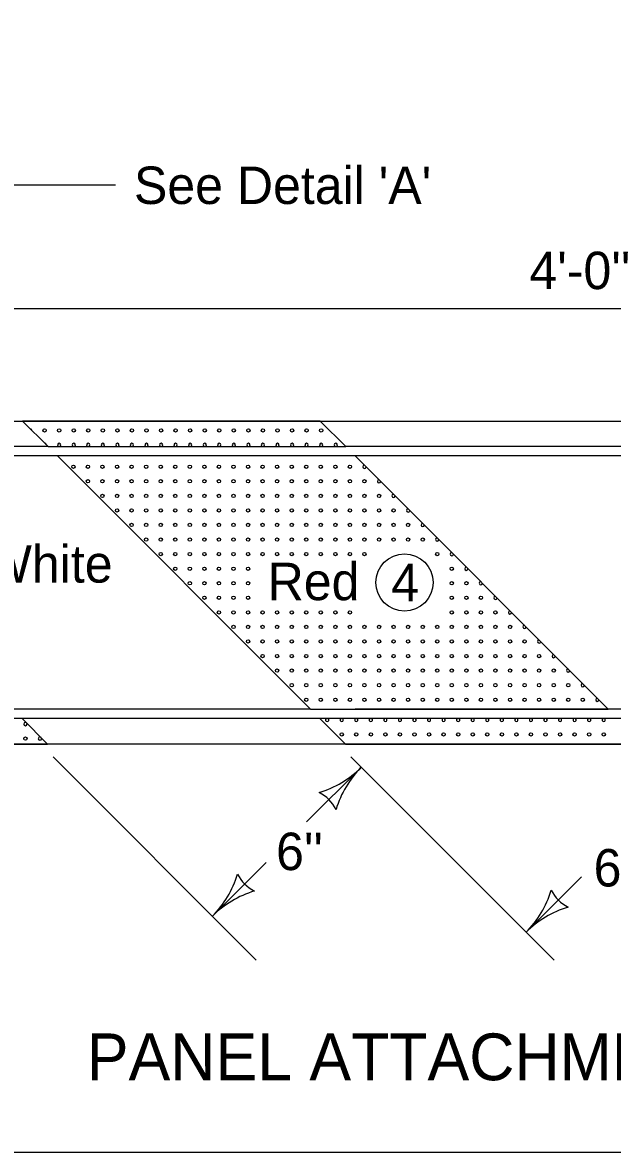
# Model space of a CAD drawing. Extents: x 228 to 3572, y -1307 to 1277.
# Drawn here: x 1955.3 to 2207.4, y -1020 to -537.2 of the extents above; entities that cross this region are included whole.
import ezdxf

# ---------------------------------------------------------------- set-up
doc = ezdxf.new("R2010")
doc.units = 0
for name, color, linetype in [('dsnStdBorder', 7, 'Continuous'), ('dsnStdDimension', 7, 'Continuous'), ('Level 2', 7, 'Continuous'), ('Level 3', 7, 'Continuous')]:
    doc.layers.add(name, color=color, linetype=linetype)

msp = doc.modelspace()

# ---------------------------------------------------------------- linework, layer by layer
at = {"layer": 'dsnStdBorder'}
msp.add_lwpolyline([(332.48, 990.01), (3467.48, 990.01), (3467.48, -1019.99), (332.48, -1019.99)], close=True, dxfattribs=at)
at = {"layer": 'dsnStdDimension'}
for p, q in [((1949.92, -606.46), (1995.05, -606.46)), ((2559.99, -659.46), (1827.99, -659.46)), ((2055.2, -937.89), (1968.29, -850.98)), ((2182.48, -937.89), (2095.57, -850.98)), ((2076.7, -878.78), (2100.05, -855.43)), ((2036.41, -919.06), (2059.41, -896.08)), ((2170.52, -925.93), (2194.17, -902.28))]:
    msp.add_line(p, q, dxfattribs=at)
for centre, radius, start, end in [((2069.52, -824.89), 43.18, 286.9257, 314.9982), ((2130.59, -885.96), 43.18, 134.9982, 163.0707), ((2074.45, -881.03), 16.68, 27.2649, 62.7316), ((2005.88, -888.53), 43.18, 314.9982, 343.0707), ((2062.01, -893.46), 16.68, 207.2649, 242.7316), ((2066.94, -949.6), 43.18, 106.9257, 134.9982), ((2139.99, -895.4), 43.18, 315, 343.0725), ((2196.12, -900.33), 16.68, 207.2667, 242.7334), ((2201.05, -956.47), 43.18, 106.9275, 135)]:
    msp.add_arc(centre, radius, start, end, dxfattribs=at)
at = {"layer": 'Level 2'}
for p, q in [((1955.27, -707.46), (1966.17, -718.36)), ((2082.55, -707.46), (1955.27, -707.46)), ((1965.99, -707.46), (2093.27, -707.46)), ((2093.45, -718.36), (2082.55, -707.46)), ((1966.17, -718.36), (1860.39, -718.36)), ((1966.17, -718.36), (2093.45, -718.36)), ((2220.73, -718.36), (2093.45, -718.36)), ((2078.37, -722.36), (1860.39, -722.36)), ((2097.45, -722.36), (1970.17, -722.36)), ((1970.17, -722.36), (2078.37, -830.56)), ((2205.65, -830.56), (2097.45, -722.36)), ((2224.73, -722.36), (2097.45, -722.36)), ((2078.37, -830.56), (1860.39, -830.56)), ((2082.37, -834.56), (1860.39, -834.56)), ((1965.99, -845.46), (1955.09, -834.56)), ((2078.37, -830.56), (2205.65, -830.56)), ((2209.65, -834.56), (2082.37, -834.56)), ((2082.37, -834.56), (2093.27, -845.46)), ((2336.93, -834.56), (2093.45, -834.56)), ((2332.93, -830.56), (2097.45, -830.56)), ((1827.99, -845.46), (1965.99, -845.46)), ((2209.83, -845.46), (1960.08, -845.46)), ((2093.27, -845.46), (2220.55, -845.46))]:
    msp.add_line(p, q, dxfattribs=at)
msp.add_lwpolyline([(1827.99, -707.46), (2559.99, -707.46), (2559.99, -845.46), (1827.99, -845.46)], close=True, dxfattribs=at)
for centre, radius in [((1964.69, -711.43), 0.711), ((1970.91, -711.43), 0.711), ((1977.13, -711.43), 0.711), ((1983.36, -711.43), 0.711), ((1989.58, -711.43), 0.711), ((1995.8, -711.43), 0.711), ((2002.02, -711.43), 0.711), ((2008.25, -711.43), 0.711), ((2014.47, -711.43), 0.711), ((2020.69, -711.43), 0.711), ((2026.91, -711.43), 0.711), ((2033.14, -711.43), 0.711), ((2039.36, -711.43), 0.711), ((2045.58, -711.43), 0.711), ((2051.8, -711.43), 0.711), ((2058.03, -711.43), 0.711), ((2064.25, -711.43), 0.711), ((2070.47, -711.43), 0.711), ((2076.69, -711.43), 0.711), ((2082.92, -711.43), 0.711), ((1976.99, -726.97), 0.711), ((1983.21, -726.97), 0.711), ((1989.43, -726.97), 0.711), ((1995.66, -726.97), 0.711), ((2001.88, -726.97), 0.711), ((2008.1, -726.97), 0.711), ((2014.32, -726.97), 0.711), ((2020.55, -726.97), 0.711), ((2026.77, -726.97), 0.711), ((2032.99, -726.97), 0.711), ((2039.21, -726.97), 0.711), ((2045.44, -726.97), 0.711), ((2051.66, -726.97), 0.711), ((2057.88, -726.97), 0.711), ((2064.1, -726.97), 0.711), ((2070.33, -726.97), 0.711), ((2076.55, -726.97), 0.711), ((2082.77, -726.97), 0.711), ((2088.99, -726.97), 0.711), ((2095.22, -726.97), 0.711), ((1983.21, -733.19), 0.711), ((1989.43, -733.19), 0.711), ((1995.66, -733.19), 0.711), ((2001.88, -733.19), 0.711), ((2008.1, -733.19), 0.711), ((2014.32, -733.19), 0.711), ((2020.55, -733.19), 0.711), ((2026.77, -733.19), 0.711), ((2032.99, -733.19), 0.711), ((2039.21, -733.19), 0.711), ((2045.44, -733.19), 0.711), ((2051.66, -733.19), 0.711), ((2057.88, -733.19), 0.711), ((2064.1, -733.19), 0.711), ((2070.33, -733.19), 0.711), ((2076.55, -733.19), 0.711), ((2082.77, -733.19), 0.711), ((2088.99, -733.19), 0.711), ((2095.22, -733.19), 0.711), ((2101.44, -733.19), 0.711), ((1989.43, -739.41), 0.711), ((1995.66, -739.41), 0.711), ((2001.88, -739.41), 0.711), ((2008.1, -739.41), 0.711), ((2014.32, -739.41), 0.711), ((2020.55, -739.41), 0.711), ((2026.77, -739.41), 0.711), ((2032.99, -739.41), 0.711), ((2039.21, -739.41), 0.711), ((2045.44, -739.41), 0.711), ((2051.66, -739.41), 0.711), ((2057.88, -739.41), 0.711), ((2064.1, -739.41), 0.711), ((2070.33, -739.41), 0.711), ((2076.55, -739.41), 0.711), ((2082.77, -739.41), 0.711), ((2088.99, -739.41), 0.711), ((2095.22, -739.41), 0.711), ((2101.44, -739.41), 0.711), ((2107.66, -739.41), 0.711), ((1995.66, -745.64), 0.711), ((2001.88, -745.64), 0.711), ((2008.1, -745.64), 0.711), ((2014.32, -745.64), 0.711), ((2020.55, -745.64), 0.711), ((2026.77, -745.64), 0.711), ((2032.99, -745.64), 0.711), ((2039.21, -745.64), 0.711), ((2045.44, -745.64), 0.711), ((2051.66, -745.64), 0.711), ((2057.88, -745.64), 0.711), ((2064.1, -745.64), 0.711), ((2070.33, -745.64), 0.711), ((2076.55, -745.64), 0.711), ((2082.77, -745.64), 0.711), ((2088.99, -745.64), 0.711), ((2095.22, -745.64), 0.711), ((2101.44, -745.64), 0.711), ((2107.66, -745.64), 0.711), ((2113.88, -745.64), 0.711), ((2001.88, -751.86), 0.711), ((2008.1, -751.86), 0.711), ((2014.32, -751.86), 0.711), ((2020.55, -751.86), 0.711), ((2026.77, -751.86), 0.711), ((2032.99, -751.86), 0.711), ((2039.21, -751.86), 0.711), ((2045.44, -751.86), 0.711), ((2051.66, -751.86), 0.711), ((2057.88, -751.86), 0.711), ((2064.1, -751.86), 0.711), ((2070.33, -751.86), 0.711), ((2076.55, -751.86), 0.711), ((2082.77, -751.86), 0.711), ((2088.99, -751.86), 0.711), ((2095.22, -751.86), 0.711), ((2101.44, -751.86), 0.711), ((2107.66, -751.86), 0.711), ((2113.88, -751.86), 0.711), ((2120.1, -751.86), 0.711), ((2008.1, -758.08), 0.711), ((2014.32, -758.08), 0.711), ((2020.55, -758.08), 0.711), ((2026.77, -758.08), 0.711), ((2032.99, -758.08), 0.711), ((2039.21, -758.08), 0.711), ((2045.44, -758.08), 0.711), ((2051.66, -758.08), 0.711), ((2057.88, -758.08), 0.711), ((2064.1, -758.08), 0.711), ((2070.33, -758.08), 0.711), ((2076.55, -758.08), 0.711), ((2082.77, -758.08), 0.711), ((2088.99, -758.08), 0.711), ((2095.22, -758.08), 0.711), ((2101.44, -758.08), 0.711), ((2107.66, -758.08), 0.711), ((2113.88, -758.08), 0.711), ((2120.1, -758.08), 0.711), ((2126.33, -758.08), 0.711), ((2014.32, -764.3), 0.711), ((2020.55, -764.3), 0.711), ((2026.77, -764.3), 0.711), ((2032.99, -764.3), 0.711), ((2039.21, -764.3), 0.711), ((2045.44, -764.3), 0.711), ((2051.66, -764.3), 0.711), ((2057.88, -764.3), 0.711), ((2064.1, -764.3), 0.711), ((2070.33, -764.3), 0.711), ((2076.55, -764.3), 0.711), ((2082.77, -764.3), 0.711), ((2088.99, -764.3), 0.711), ((2095.22, -764.3), 0.711), ((2101.44, -764.3), 0.711), ((2118.55, -776.43), 12.25), ((2132.55, -764.3), 0.711), ((2020.55, -770.53), 0.711), ((2026.77, -770.53), 0.711), ((2032.99, -770.53), 0.711), ((2039.21, -770.53), 0.711), ((2045.44, -770.53), 0.711), ((2051.66, -770.53), 0.711), ((2138.77, -770.53), 0.711), ((2026.77, -776.75), 0.711), ((2032.99, -776.75), 0.711), ((2039.21, -776.75), 0.711), ((2045.44, -776.75), 0.711), ((2051.66, -776.75), 0.711), ((2138.77, -776.75), 0.711), ((2144.99, -776.75), 0.711), ((2032.99, -782.97), 0.711), ((2039.21, -782.97), 0.711), ((2045.44, -782.97), 0.711), ((2051.66, -782.97), 0.711), ((2138.77, -782.97), 0.711), ((2144.99, -782.97), 0.711), ((2151.22, -782.97), 0.711), ((2039.21, -789.19), 0.711), ((2045.44, -789.19), 0.711), ((2051.66, -789.19), 0.711), ((2057.88, -789.19), 0.711), ((2064.1, -789.19), 0.711), ((2070.33, -789.19), 0.711), ((2076.55, -789.19), 0.711), ((2082.77, -789.19), 0.711), ((2088.99, -789.19), 0.711), ((2095.22, -789.19), 0.711), ((2138.77, -789.19), 0.711), ((2144.99, -789.19), 0.711), ((2151.22, -789.19), 0.711), ((2157.44, -789.19), 0.711), ((2045.44, -795.42), 0.711), ((2051.66, -795.42), 0.711), ((2057.88, -795.42), 0.711), ((2064.1, -795.42), 0.711), ((2070.33, -795.42), 0.711), ((2076.55, -795.42), 0.711), ((2082.77, -795.42), 0.711), ((2088.99, -795.42), 0.711), ((2095.22, -795.42), 0.711), ((2101.44, -795.42), 0.711), ((2107.66, -795.42), 0.711), ((2113.88, -795.42), 0.711), ((2120.1, -795.42), 0.711), ((2126.33, -795.42), 0.711), ((2132.55, -795.42), 0.711), ((2138.77, -795.42), 0.711), ((2144.99, -795.42), 0.711), ((2151.22, -795.42), 0.711), ((2157.44, -795.42), 0.711), ((2163.66, -795.42), 0.711), ((2051.66, -801.64), 0.711), ((2057.88, -801.64), 0.711), ((2064.1, -801.64), 0.711), ((2070.33, -801.64), 0.711), ((2076.55, -801.64), 0.711), ((2082.77, -801.64), 0.711), ((2088.99, -801.64), 0.711), ((2095.22, -801.64), 0.711), ((2101.44, -801.64), 0.711), ((2107.66, -801.64), 0.711), ((2113.88, -801.64), 0.711), ((2120.1, -801.64), 0.711), ((2126.33, -801.64), 0.711), ((2132.55, -801.64), 0.711), ((2138.77, -801.64), 0.711), ((2144.99, -801.64), 0.711), ((2151.22, -801.64), 0.711), ((2157.44, -801.64), 0.711), ((2163.66, -801.64), 0.711), ((2169.88, -801.64), 0.711), ((2057.88, -807.86), 0.711), ((2064.1, -807.86), 0.711), ((2070.33, -807.86), 0.711), ((2076.55, -807.86), 0.711), ((2082.77, -807.86), 0.711), ((2088.99, -807.86), 0.711), ((2095.22, -807.86), 0.711), ((2101.44, -807.86), 0.711), ((2107.66, -807.86), 0.711), ((2113.88, -807.86), 0.711), ((2120.1, -807.86), 0.711), ((2126.33, -807.86), 0.711), ((2132.55, -807.86), 0.711), ((2138.77, -807.86), 0.711), ((2144.99, -807.86), 0.711), ((2151.22, -807.86), 0.711), ((2157.44, -807.86), 0.711), ((2163.66, -807.86), 0.711), ((2169.88, -807.86), 0.711), ((2176.11, -807.86), 0.711), ((2064.1, -814.08), 0.711), ((2070.33, -814.08), 0.711), ((2076.55, -814.08), 0.711), ((2082.77, -814.08), 0.711), ((2088.99, -814.08), 0.711), ((2095.22, -814.08), 0.711), ((2101.44, -814.08), 0.711), ((2107.66, -814.08), 0.711), ((2113.88, -814.08), 0.711), ((2120.1, -814.08), 0.711), ((2126.33, -814.08), 0.711), ((2132.55, -814.08), 0.711), ((2138.77, -814.08), 0.711), ((2144.99, -814.08), 0.711), ((2151.22, -814.08), 0.711), ((2157.44, -814.08), 0.711), ((2163.66, -814.08), 0.711), ((2169.88, -814.08), 0.711), ((2176.11, -814.08), 0.711), ((2182.33, -814.08), 0.711), ((2070.33, -820.31), 0.711), ((2076.55, -820.31), 0.711), ((2082.77, -820.31), 0.711), ((2088.99, -820.31), 0.711), ((2095.22, -820.31), 0.711), ((2101.44, -820.31), 0.711), ((2107.66, -820.31), 0.711), ((2113.88, -820.31), 0.711), ((2120.1, -820.31), 0.711), ((2126.33, -820.31), 0.711), ((2132.55, -820.31), 0.711), ((2138.77, -820.31), 0.711), ((2144.99, -820.31), 0.711), ((2151.22, -820.31), 0.711), ((2157.44, -820.31), 0.711), ((2163.66, -820.31), 0.711), ((2169.88, -820.31), 0.711), ((2176.11, -820.31), 0.711), ((2182.33, -820.31), 0.711), ((2188.55, -820.31), 0.711), ((2076.55, -826.53), 0.711), ((2082.77, -826.53), 0.711), ((2088.99, -826.53), 0.711), ((2095.22, -826.53), 0.711), ((2101.44, -826.53), 0.711), ((2107.66, -826.53), 0.711), ((2113.88, -826.53), 0.711), ((2120.1, -826.53), 0.711), ((2126.33, -826.53), 0.711), ((2132.55, -826.53), 0.711), ((2138.77, -826.53), 0.711), ((2144.99, -826.53), 0.711), ((2151.22, -826.53), 0.711), ((2157.44, -826.53), 0.711), ((2163.66, -826.53), 0.711), ((2169.88, -826.53), 0.711), ((2176.11, -826.53), 0.711), ((2182.33, -826.53), 0.711), ((2188.55, -826.53), 0.711), ((2194.77, -826.53), 0.711), ((1956.48, -843.17), 0.711), ((2091.72, -841.35), 0.711), ((2097.94, -841.35), 0.711), ((2104.17, -841.35), 0.711), ((2110.39, -841.35), 0.711), ((2116.61, -841.35), 0.711), ((2122.83, -841.35), 0.711), ((2129.06, -841.35), 0.711), ((2135.28, -841.35), 0.711), ((2141.5, -841.35), 0.711), ((2147.72, -841.35), 0.711), ((2153.94, -841.35), 0.711), ((2160.17, -841.35), 0.711), ((2166.39, -841.35), 0.711), ((2172.61, -841.35), 0.711), ((2178.83, -841.35), 0.711), ((2185.06, -841.35), 0.711), ((2191.28, -841.35), 0.711), ((2197.5, -841.35), 0.711), ((2203.72, -841.35), 0.711)]:
    msp.add_circle(centre, radius, dxfattribs=at)
for centre, start, end in [((1958.47, -711.43), 5.8153, 84.1847), ((1964.69, -717.66), 5.7815, 84.1847), ((1970.91, -717.66), 280.3616, 259.6384), ((1977.13, -717.66), 280.3616, 259.6384), ((1983.36, -717.66), 280.3616, 259.6384), ((1989.58, -717.66), 280.3616, 259.6384), ((1995.8, -717.66), 280.3616, 259.6384), ((2002.02, -717.66), 280.3616, 259.6384), ((2008.25, -717.66), 280.3616, 259.6384), ((2014.47, -717.66), 280.3616, 259.6384), ((2020.69, -717.66), 280.3616, 259.6384), ((2026.91, -717.66), 280.3616, 259.6384), ((2033.14, -717.66), 280.3616, 259.6384), ((2039.36, -717.66), 280.3616, 259.6384), ((2045.58, -717.66), 280.3616, 259.6384), ((2051.8, -717.66), 280.3616, 259.6384), ((2058.03, -717.66), 280.3616, 259.6384), ((2064.25, -717.66), 280.3616, 259.6384), ((2070.47, -717.66), 280.3616, 259.6384), ((2076.69, -717.66), 280.3616, 259.6384), ((2082.92, -717.66), 280.3616, 259.6384), ((2089.14, -717.66), 280.3616, 259.6384), ((2101.44, -726.97), 96.5668, 353.4332), ((2107.66, -733.19), 96.5668, 353.4332), ((2113.88, -739.41), 96.5668, 353.4332), ((2120.1, -745.64), 96.5668, 353.4332), ((2126.33, -751.86), 96.5668, 353.4332), ((2132.55, -758.08), 96.5668, 353.4332), ((2138.77, -764.3), 96.5668, 353.4332), ((2144.99, -770.53), 96.5668, 353.4332), ((2151.22, -776.75), 96.5668, 353.4332), ((2157.44, -782.97), 96.5668, 353.4332), ((2163.66, -789.19), 96.5668, 353.4332), ((2169.88, -795.42), 96.5668, 353.4332), ((2176.11, -801.64), 96.5668, 353.4332), ((2182.33, -807.86), 96.5668, 353.4332), ((2188.55, -814.08), 96.5668, 353.4332), ((2194.77, -820.31), 96.5668, 353.4332), ((2201, -826.53), 96.5668, 353.4332), ((2085.5, -835.13), 126.6764, 53.3236), ((2091.72, -835.13), 126.6764, 53.3236), ((2097.94, -835.13), 126.6764, 53.3236), ((2104.17, -835.13), 126.6764, 53.3236), ((2110.39, -835.13), 126.6764, 53.3236), ((2116.61, -835.13), 126.6764, 53.3236), ((2122.83, -835.13), 126.6764, 53.3236), ((2129.06, -835.13), 126.6764, 53.3236), ((2135.28, -835.13), 126.6764, 53.3236), ((2141.5, -835.13), 126.6764, 53.3236), ((2147.72, -835.13), 126.6764, 53.3236), ((2153.94, -835.13), 126.6764, 53.3236), ((2160.17, -835.13), 126.6764, 53.3236), ((2166.39, -835.13), 126.6764, 53.3236), ((2172.61, -835.13), 126.6764, 53.3236), ((2178.83, -835.13), 126.6764, 53.3236), ((2185.06, -835.13), 126.6764, 53.3236), ((2191.28, -835.13), 126.6764, 53.3236), ((2197.5, -835.13), 126.6764, 53.3236), ((2203.72, -835.13), 126.6764, 53.3236), ((1956.48, -836.94), 51.1501, 38.8499), ((1962.7, -843.17), 51.1501, 38.8499)]:
    msp.add_arc(centre, 0.711, start, end, dxfattribs=at)

# ---------------------------------------------------------------- texts
at = {"layer": 'dsnStdDimension'}
for s, p in [("See Detail 'A'", (2002.88, -614.68)), ("4'-0''", (2171.96, -651.07)), ("6''", (2063.64, -899.35)), ("6''", (2199.4, -906.35))]:
    msp.add_text(s, height=16, dxfattribs=at).set_placement(p)
at = {"layer": 'Level 3'}
for s, height, p in [('White', 16, (1939.06, -776.49)), ('Red', 16, (2060.04, -783.99)), ('4', 16, (2112.88, -784.43)), ('PANEL ATTACHMENT DETAILS', 20, (1982.75, -989.16))]:
    msp.add_text(s, height=height, dxfattribs=at).set_placement(p)

doc.saveas('drawing.dxf')
